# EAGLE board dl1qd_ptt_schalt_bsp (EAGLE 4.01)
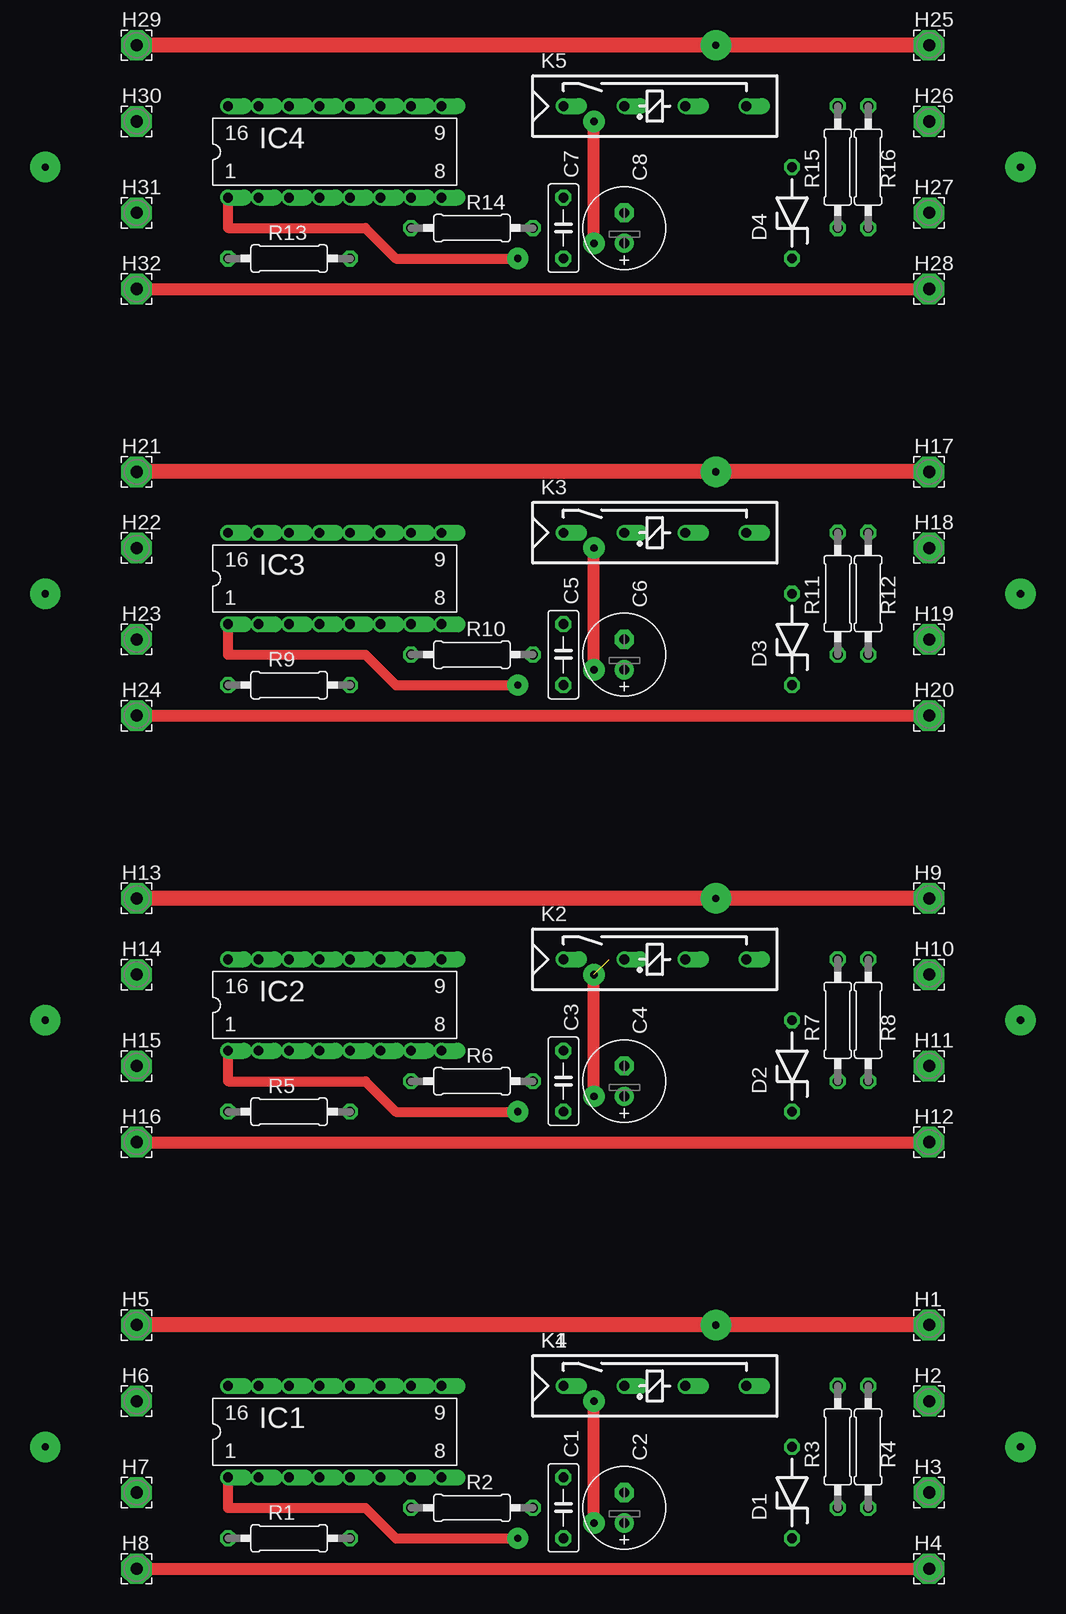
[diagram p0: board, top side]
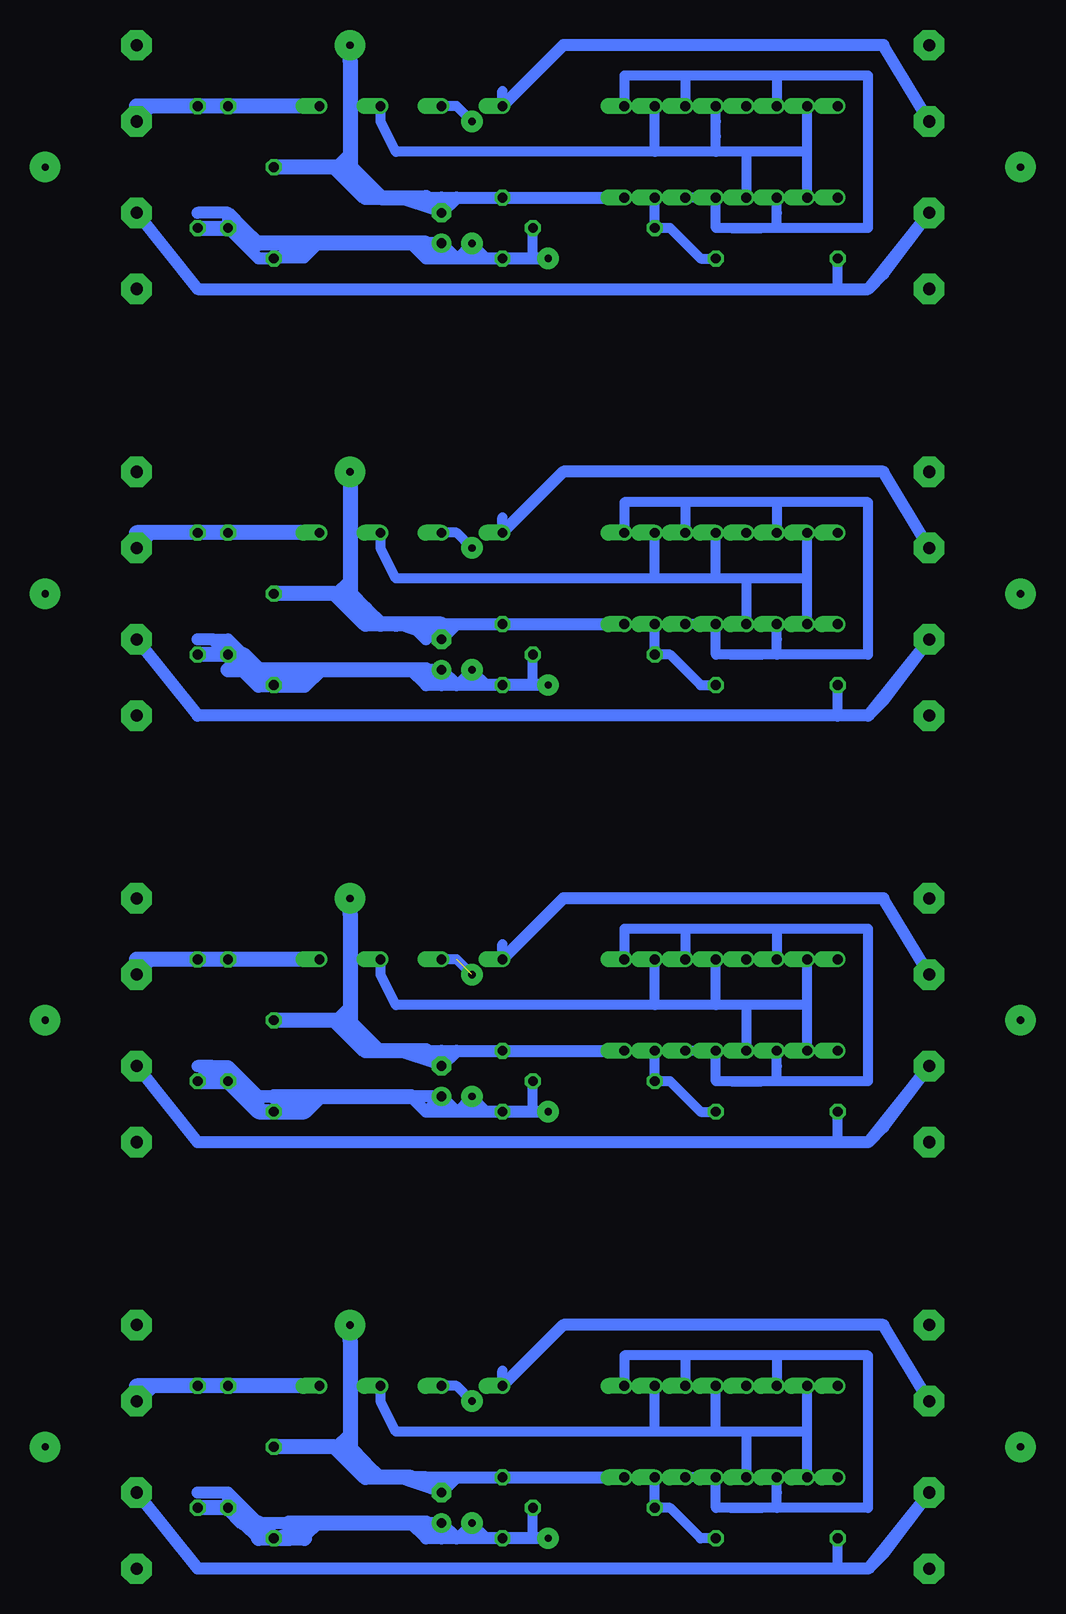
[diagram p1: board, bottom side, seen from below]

No outline drawn. Coordinates in mm, seen from the top.
Copper layers used: Top, Bottom

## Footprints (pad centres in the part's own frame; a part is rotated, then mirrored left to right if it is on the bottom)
C050-025X075 = drill 0.813 octagon: 1 -2.54,0; 2 2.54,0
E2,5-7 = drill 0.813 pad 1.6 round: + -1.27,0 | drill 0.813 pad 1.6 octagon: - 1.27,0
ZDIO-7.5 = drill 0.813 octagon: A -3.81,0; K 3.81,0
2,54/1,0 = drill 1.016 pad 2.54 octagon: 1 0,0
DIL16 = drill 0.813 offset: 1 -8.89,-3.81; 2 -6.35,-3.81; 3 -3.81,-3.81; 4 -1.27,-3.81; 5 1.27,-3.81; 6 3.81,-3.81; 7 6.35,-3.81; 8 8.89,-3.81; 9 8.89,3.81; 10 6.35,3.81; 11 3.81,3.81; 12 1.27,3.81; 13 -1.27,3.81; 14 -3.81,3.81; 15 -6.35,3.81; 16 -8.89,3.81
REED = drill 0.813 offset: 1 -17.78,2.54; 3 -12.7,2.54; 5 -7.62,2.54; 7 -2.54,2.54
0207/10 = drill 0.813 octagon: 1 -5.08,0; 2 5.08,0

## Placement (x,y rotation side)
C1  0.1µ  [C050-025X075]  48.26,69.85 90 top
C2  100µ  [E2,5-7]  53.34,69.85 90 top
C3  0.1µ  [C050-025X075]  48.26,105.41 90 top
C4  100µ  [E2,5-7]  53.34,105.41 90 top
C5  0.1µ  [C050-025X075]  48.26,140.97 90 top
C6  100µ  [E2,5-7]  53.34,140.97 90 top
C7  0.1µ  [C050-025X075]  48.26,176.53 90 top
C8  100µ  [E2,5-7]  53.34,176.53 90 top
D1  5.1  [ZDIO-7.5]  67.31,71.12 270 top
D2  5.1  [ZDIO-7.5]  67.31,106.68 270 top
D3  5.1  [ZDIO-7.5]  67.31,142.24 270 top
D4  5.1  [ZDIO-7.5]  67.31,177.8 270 top
H1  [2,54/1,0]  78.74,85.09 0 top
H2  [2,54/1,0]  78.74,78.74 0 top
H3  [2,54/1,0]  78.74,71.12 0 top
H4  [2,54/1,0]  78.74,64.77 0 top
H5  [2,54/1,0]  12.7,85.09 0 top
H6  [2,54/1,0]  12.7,78.74 0 top
H7  [2,54/1,0]  12.7,71.12 0 top
H8  [2,54/1,0]  12.7,64.77 0 top
H9  [2,54/1,0]  78.74,120.65 0 top
H10  [2,54/1,0]  78.74,114.3 0 top
H11  [2,54/1,0]  78.74,106.68 0 top
H12  [2,54/1,0]  78.74,100.33 0 top
H13  [2,54/1,0]  12.7,120.65 0 top
H14  [2,54/1,0]  12.7,114.3 0 top
H15  [2,54/1,0]  12.7,106.68 0 top
H16  [2,54/1,0]  12.7,100.33 0 top
H17  [2,54/1,0]  78.74,156.21 0 top
H18  [2,54/1,0]  78.74,149.86 0 top
H19  [2,54/1,0]  78.74,142.24 0 top
H20  [2,54/1,0]  78.74,135.89 0 top
H21  [2,54/1,0]  12.7,156.21 0 top
H22  [2,54/1,0]  12.7,149.86 0 top
H23  [2,54/1,0]  12.7,142.24 0 top
H24  [2,54/1,0]  12.7,135.89 0 top
H25  [2,54/1,0]  78.74,191.77 0 top
H26  [2,54/1,0]  78.74,185.42 0 top
H27  [2,54/1,0]  78.74,177.8 0 top
H28  [2,54/1,0]  78.74,171.45 0 top
H29  [2,54/1,0]  12.7,191.77 0 top
H30  [2,54/1,0]  12.7,185.42 0 top
H31  [2,54/1,0]  12.7,177.8 0 top
H32  [2,54/1,0]  12.7,171.45 0 top
IC1  4049  [DIL16]  29.21,76.2 0 top
IC2  4049  [DIL16]  29.21,111.76 0 top
IC3  4049  [DIL16]  29.21,147.32 0 top
IC4  4049  [DIL16]  29.21,182.88 0 top
K1  [REED]  66.04,77.47 0 top
K2  [REED]  66.04,113.03 0 top
K3  [REED]  66.04,148.59 0 top
K4  [REED]  66.04,77.47 0 top
K5  [REED]  66.04,184.15 0 top
R1  56k  [0207/10]  25.4,67.31 0 top
R2  1M  [0207/10]  40.64,69.85 0 top
R3  1k  [0207/10]  71.12,74.93 90 top
R4  1k  [0207/10]  73.66,74.93 90 top
R5  56k  [0207/10]  25.4,102.87 0 top
R6  1M  [0207/10]  40.64,105.41 0 top
R7  1k  [0207/10]  71.12,110.49 90 top
R8  1k  [0207/10]  73.66,110.49 90 top
R9  56k  [0207/10]  25.4,138.43 0 top
R10  1M  [0207/10]  40.64,140.97 0 top
R11  1k  [0207/10]  71.12,146.05 90 top
R12  1k  [0207/10]  73.66,146.05 90 top
R13  56k  [0207/10]  25.4,173.99 0 top
R14  1M  [0207/10]  40.64,176.53 0 top
R15  1k  [0207/10]  71.12,181.61 90 top
R16  1k  [0207/10]  73.66,181.61 90 top

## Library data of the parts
C1-C8 R1-R16 = rcl
D1-D4 = diode
H1-H32 = wirepad
IC1-IC4 = 40xx
K1-K5 = relay

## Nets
S$1: C2.+ D1.K IC1.1 K1.3 R2.2 R3.1 R4.1
S$2: IC1.2 IC1.4 IC1.10 IC1.12 IC1.15 K1.5
S$3: IC1.3 IC1.5 IC1.6 IC1.9 IC1.11 IC1.14
S$4: H4.1 H8.1
S$6: C1.2 C2.- D1.A H1.1 H5.1 IC1.8
S$7: IC1.7 R2.1
S$8: H3.1 H7.1 R1.1
S$9: R1.2
S$11: H2.1 K1.7
S$12: H6.1 K1.1

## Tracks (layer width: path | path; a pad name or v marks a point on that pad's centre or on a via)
S$1  (via drill 0.61 pad 1.78)
  Top 0.813: v44.45,67.31 34.29,67.31 31.75,69.85 20.32,69.85 IC1.1
  Top 1.016: v50.8,68.58 v50.8,78.74
  Bottom 0.813: 66.04,67.31 64.77,67.31 63.5,68.58 | K1.3 52.07,80.01 v50.8,78.74 | 49.53,67.31 v50.8,68.58 | 50.8,67.31 v50.8,68.58 | 50.8,67.31 49.53,67.31 | 52.07,67.31 50.8,67.31 | 52.07,67.31 49.53,67.31 | 52.07,67.31 v50.8,68.58 | 48.26,67.31 49.53,67.31 | 45.72,67.31 R2.2 | 45.72,67.31 48.26,67.31 | 45.72,67.31 v44.45,67.31 48.26,67.31 | R3.1 R4.1 R3.1
  Bottom 1.016: 71.12,71.12 73.66,71.12 | R4.1 R3.1 71.12,71.12 | 69.85,69.85 71.12,71.12 | 69.85,69.85 69.85,68.58 68.58,67.31 D1.K 63.5,68.58 | 69.85,69.85 68.58,68.58 66.04,68.58 63.5,68.58 | 55.88,68.58 63.5,68.58 | 54.61,67.31 55.88,68.58 | 55.88,68.58 54.61,68.58 C2.+ | C2.+ 54.61,67.31 | 53.34,67.31 54.61,67.31 | 53.34,67.31 C2.+ | 52.07,67.31 53.34,67.31 | 52.07,67.31 C2.+ | v44.45,67.31 52.07,67.31
  Bottom 1.27: R3.1 R4.1 R3.1 | R3.1 69.85,68.58 68.58,68.58 D1.K 66.04,67.31 | 64.77,67.31 68.58,67.31 | 54.61,68.58 66.04,68.58
S$2
  Bottom 0.813: IC1.2 22.86,76.2 | 22.86,76.2 IC1.15 | 22.86,76.2 27.94,76.2 | 27.94,76.2 30.48,76.2 | 30.48,76.2 35.56,76.2 | 35.56,76.2 IC1.10 | 35.56,76.2 57.15,76.2 58.42,78.74 K1.5 | 27.94,76.2 IC1.4 | 30.48,76.2 IC1.12
S$3
  Bottom 0.61: 25.4,71.12 IC1.3
  Bottom 0.813: 25.4,82.55 17.78,82.55 17.78,69.85 25.4,69.85 | 25.4,82.55 IC1.14 | 25.4,82.55 33.02,82.55 | 33.02,82.55 IC1.11 | 33.02,82.55 38.1,82.55 IC1.9 | IC1.6 IC1.5 30.48,69.85 29.21,69.85 | 29.21,69.85 26.67,69.85 | 25.4,69.85 25.4,71.12 | 25.4,69.85 IC1.3 | 25.4,69.85 29.21,69.85
S$4
  Top 1.016: H8.1 H4.1
S$5
  Bottom 0.813: 22.86,143.51 22.86,147.32 | 22.86,147.32 22.86,151.13 | 22.86,147.32 27.94,147.32 | 27.94,147.32 30.48,147.32 | 30.48,147.32 35.56,147.32 | 35.56,147.32 35.56,151.13 | 35.56,147.32 57.15,147.32 58.42,149.86 58.42,151.13 | 30.48,147.32 30.48,151.13 | 27.94,147.32 27.94,143.51
S$6  (via drill 0.61 pad 2.54)
  Top 1.016: H1.1 v60.96,85.09 H5.1
  Top 1.27: H1.1 H5.1
  Bottom 0.813: 60.96,74.93 60.96,76.2 62.23,74.93 60.96,73.66 | 57.15,72.39 C2.- 54.61,72.39 53.34,72.39 52.07,72.39 C1.2 IC1.8
  Bottom 1.016: 60.96,74.93 62.23,74.93 | 53.34,72.39 C2.- 52.07,72.39 | 52.07,72.39 IC1.8 | 52.07,72.39 54.61,72.39 55.88,72.39 57.15,72.39 | 57.15,72.39 58.42,72.39 59.69,73.66 | 60.96,74.93 59.69,73.66 | 59.69,73.66 59.69,72.39 | 59.69,72.39 57.15,72.39 | v60.96,85.09 60.96,83.82 | 59.69,72.39 60.96,73.66 60.96,74.93
  Bottom 1.27: D1.A 62.23,74.93 59.69,72.39 55.88,72.39 | 60.96,83.82 60.96,74.93
S$7
  Bottom 0.813: R2.1 IC1.7
S$8
  Bottom 0.813: 20.32,64.77 R1.1
  Bottom 1.016: 17.78,64.77 20.32,64.77 73.66,64.77 | 17.78,64.77 16.51,66.04 H7.1 17.78,64.77 | 73.66,64.77 H3.1 | 17.78,64.77 73.66,64.77
S$9
  Bottom 0.813: R1.2 31.75,67.31 34.29,69.85 35.56,69.85
S$10  (via drill 0.61 pad 2.54)
  other vias: 5.08,74.93
S$11
  Bottom 1.27: K1.7 77.47,80.01 | 77.47,80.01 H2.1 | 77.47,80.01 78.74,80.01
S$12
  Bottom 0.813: K1.1 48.26,81.28
  Bottom 1.016: K1.1 43.18,85.09 16.51,85.09 H6.1
S$13  (via drill 0.61 pad 2.54)
  other vias: 86.36,74.93
S$14
  Bottom 0.813: 22.86,107.95 22.86,111.76 | 22.86,111.76 22.86,115.57 | 22.86,111.76 27.94,111.76 | 27.94,111.76 30.48,111.76 | 30.48,111.76 35.56,111.76 | 35.56,111.76 35.56,115.57 | 35.56,111.76 57.15,111.76 58.42,114.3 58.42,115.57 | 27.94,111.76 27.94,107.95 | 30.48,111.76 30.48,115.57
S$15
  Bottom 0.61: 25.4,106.68 25.4,107.95
  Bottom 0.813: 25.4,118.11 17.78,118.11 17.78,105.41 25.4,105.41 | 25.4,118.11 25.4,115.57 | 25.4,118.11 33.02,118.11 | 33.02,118.11 33.02,115.57 | 33.02,118.11 38.1,118.11 38.1,115.57 | 33.02,107.95 30.48,107.95 30.48,105.41 29.21,105.41 | 29.21,105.41 26.67,105.41 | 25.4,105.41 25.4,106.68 | 25.4,105.41 25.4,107.95 | 25.4,105.41 29.21,105.41
S$16
  Bottom 0.813: 53.34,115.57 52.07,115.57 50.8,114.3
S$17
  Bottom 0.813: 35.56,105.41 35.56,107.95
S$18
  Bottom 0.813: 20.32,100.33 20.32,102.87
  Bottom 1.016: 17.78,100.33 20.32,100.33 73.66,100.33 | 17.78,100.33 16.51,101.6 12.7,106.68 17.78,100.33 | 73.66,100.33 78.74,106.68 | 17.78,100.33 73.66,100.33
S$19
  Top 1.016: 12.7,100.33 78.74,100.33
S$20  (via drill 0.61 pad 1.78)  (1 unrouted)
  Top 0.813: v44.45,102.87 34.29,102.87 31.75,105.41 20.32,105.41 20.32,107.95
  Top 1.016: v50.8,104.14 50.8,114.3
  Bottom 0.813: 67.31,102.87 66.04,102.87 | 50.8,102.87 49.53,102.87 | v50.8,104.14 50.8,102.87 | v50.8,104.14 49.53,102.87 | 52.07,102.87 v50.8,104.14 | 52.07,102.87 50.8,102.87 | 52.07,102.87 49.53,102.87 | 48.26,102.87 49.53,102.87 | 45.72,102.87 45.72,105.41 | 45.72,102.87 48.26,102.87 | 45.72,102.87 v44.45,102.87 48.26,102.87
  Bottom 1.016: 63.5,104.14 67.31,102.87 68.58,102.87 | 54.61,102.87 55.88,104.14 53.34,104.14 | 53.34,104.14 54.61,102.87 | 53.34,102.87 54.61,102.87 | 53.34,102.87 53.34,104.14 | 52.07,102.87 53.34,102.87 | 52.07,102.87 53.34,104.14 | v44.45,102.87 52.07,102.87 | 71.12,105.41 69.85,105.41 68.58,104.14 | 68.58,102.87 68.58,104.14 | 69.85,104.14 68.58,102.87 | 72.39,106.68 73.66,105.41 | 72.39,106.68 71.12,106.68 68.58,104.14 | 68.58,104.14 67.31,104.14 | 67.31,104.14 64.77,104.14 | 67.31,104.14 69.85,104.14 | 69.85,104.14 71.12,105.41 | 71.12,105.41 72.39,106.68 | 72.39,106.68 73.66,106.68
  Bottom 1.27: 68.58,102.87 71.12,105.41 73.66,105.41 | 68.58,102.87 66.04,102.87 | 66.04,102.87 64.77,102.87 | 67.31,104.14 63.5,104.14 | 63.5,104.14 55.88,104.14 | 66.04,102.87 64.77,104.14 63.5,104.14 | 63.5,104.14 64.77,102.87 | 64.77,102.87 68.58,102.87
S$21
  Bottom 0.813: 30.48,102.87 31.75,102.87 34.29,105.41 35.56,105.41
S$22
  Bottom 1.016: 78.74,114.3 77.47,115.57 64.77,115.57 63.5,115.57
  Bottom 1.27: 64.77,115.57 78.74,115.57 78.74,114.3
S$23
  Bottom 0.813: 48.26,115.57 48.26,116.84
  Bottom 1.016: 48.26,115.57 43.18,120.65 16.51,120.65 12.7,114.3
S$24  (via drill 0.61 pad 2.54)
  Top 1.016: 78.74,120.65 v60.96,120.65 12.7,120.65
  Top 1.27: 78.74,120.65 12.7,120.65
  Bottom 0.813: 60.96,110.49 60.96,111.76 62.23,110.49 60.96,109.22 | 58.42,107.95 57.15,107.95 | 57.15,107.95 53.34,106.68 54.61,107.95 53.34,107.95 52.07,107.95 | 57.15,107.95 55.88,107.95
  Bottom 1.016: 60.96,110.49 62.23,110.49 | 53.34,107.95 53.34,106.68 52.07,107.95 | 52.07,107.95 38.1,107.95 | 55.88,107.95 54.61,107.95 | 54.61,107.95 52.07,107.95 | 54.61,107.95 58.42,107.95 | 58.42,107.95 59.69,107.95 60.96,109.22 60.96,110.49 | 60.96,110.49 60.96,119.38 v60.96,120.65 | 60.96,110.49 58.42,107.95
  Bottom 1.27: 67.31,110.49 62.23,110.49 59.69,107.95 54.61,107.95 | 60.96,119.38 60.96,109.22
S$25  (via drill 0.61 pad 2.54)
  other vias: 5.08,110.49
S$26  (via drill 0.61 pad 2.54)
  other vias: 86.36,110.49
S$27
  Bottom 0.61: 25.4,142.24 25.4,143.51
  Bottom 0.813: 25.4,153.67 17.78,153.67 17.78,140.97 25.4,140.97 | 25.4,153.67 25.4,151.13 | 25.4,153.67 33.02,153.67 | 33.02,153.67 33.02,151.13 | 33.02,153.67 38.1,153.67 38.1,151.13 | 33.02,143.51 30.48,143.51 30.48,140.97 29.21,140.97 | 29.21,140.97 26.67,140.97 | 25.4,140.97 25.4,142.24 | 25.4,140.97 25.4,143.51 | 25.4,140.97 29.21,140.97
S$28  (via drill 0.61 pad 1.78)
  Top 0.813: v44.45,138.43 34.29,138.43 31.75,140.97 20.32,140.97 20.32,143.51
  Top 1.016: v50.8,139.7 v50.8,149.86
  Bottom 0.813: 50.8,138.43 49.53,138.43 | v50.8,139.7 50.8,138.43 | v50.8,139.7 49.53,138.43 | 52.07,138.43 v50.8,139.7 | 52.07,138.43 50.8,138.43 | 52.07,138.43 49.53,138.43 | 48.26,138.43 49.53,138.43 | 45.72,138.43 45.72,140.97 | 45.72,138.43 48.26,138.43 | 45.72,138.43 v44.45,138.43 48.26,138.43 | 53.34,151.13 52.07,151.13 v50.8,149.86
  Bottom 1.016: 69.85,139.7 68.58,138.43 67.31,139.7 68.58,139.7 69.85,139.7 | 69.85,139.7 71.12,140.97 72.39,142.24 | 63.5,139.7 67.31,138.43 | 54.61,138.43 55.88,139.7 | 53.34,139.7 54.61,139.7 | 53.34,139.7 54.61,138.43 | 53.34,138.43 54.61,138.43 | 53.34,138.43 53.34,139.7 | 52.07,138.43 53.34,138.43 | 52.07,138.43 53.34,139.7 | v44.45,138.43 52.07,138.43 | 69.85,139.7 69.85,140.97 71.12,142.24 72.39,142.24 | 72.39,142.24 73.66,142.24
  Bottom 1.27: 66.04,139.7 67.31,139.7 | 64.77,139.7 66.04,139.7 | 54.61,139.7 55.88,139.7 63.5,139.7 | 66.04,139.7 71.12,139.7 | 71.12,140.97 69.85,140.97 | 69.85,140.97 68.58,139.7 68.58,138.43 | 68.58,138.43 67.31,138.43 66.04,138.43 | 68.58,138.43 71.12,140.97 | 71.12,140.97 73.66,140.97 | 63.5,139.7 64.77,139.7 | 64.77,139.7 66.04,138.43 | 66.04,138.43 64.77,138.43 63.5,139.7 | 71.12,140.97 69.85,140.97
S$29
  Bottom 0.813: 35.56,140.97 35.56,143.51
S$30
  Bottom 0.813: 20.32,135.89 20.32,138.43
  Bottom 1.016: 17.78,135.89 20.32,135.89 73.66,135.89 | 17.78,135.89 16.51,137.16 12.7,142.24 17.78,135.89 | 73.66,135.89 78.74,142.24 | 17.78,135.89 73.66,135.89
S$31
  Top 1.016: 12.7,135.89 78.74,135.89
S$32  (via drill 0.61 pad 1.78)  (1 unrouted)
  Bottom 0.813: 52.07,115.57 53.34,115.57
  other vias: 50.8,114.3
S$33
  Bottom 0.813: 30.48,138.43 31.75,138.43 34.29,140.97 35.56,140.97
S$34
  Bottom 1.016: 78.74,149.86 77.47,151.13 63.5,151.13
  Bottom 1.27: 63.5,151.13 78.74,151.13 78.74,149.86
S$35
  Bottom 0.813: 48.26,151.13 48.26,152.4
  Bottom 1.016: 48.26,151.13 43.18,156.21 16.51,156.21 12.7,149.86
S$36  (via drill 0.61 pad 2.54)
  Top 1.016: 78.74,156.21 v60.96,156.21 12.7,156.21
  Top 1.27: 78.74,156.21 12.7,156.21
  Bottom 0.813: 60.96,146.05 60.96,147.32 62.23,146.05 60.96,144.78 | 57.15,143.51 53.34,142.24 54.61,143.51
  Bottom 1.016: 62.23,146.05 60.96,146.05 58.42,143.51 | 53.34,143.51 53.34,142.24 52.07,143.51 | 52.07,143.51 38.1,143.51 | 55.88,143.51 54.61,143.51 53.34,143.51 | 53.34,143.51 52.07,143.51 | 54.61,142.24 55.88,143.51 | 60.96,144.78 59.69,143.51 58.42,143.51 | 58.42,143.51 57.15,143.51 55.88,143.51
  Bottom 1.27: 67.31,146.05 62.23,146.05 59.69,143.51 | v60.96,156.21 60.96,146.05 | 60.96,146.05 60.96,144.78 59.69,144.78 | 59.69,144.78 58.42,143.51 | 53.34,143.51 57.15,143.51 59.69,143.51 | 59.69,143.51 59.69,144.78 | 59.69,144.78 60.96,146.05
S$37  (via drill 0.61 pad 2.54)
  other vias: 5.08,146.05
S$38  (via drill 0.61 pad 2.54)
  other vias: 86.36,146.05
S$39
  Bottom 0.406: 30.48,185.42 30.48,186.69
  Bottom 0.813: 22.86,179.07 22.86,182.88 | 22.86,182.88 22.86,186.69 | 22.86,182.88 27.94,182.88 | 27.94,182.88 30.48,182.88 | 30.48,184.15 30.48,185.42 | 30.48,182.88 30.48,184.15 | 30.48,182.88 35.56,182.88 | 35.56,182.88 35.56,186.69 | 35.56,182.88 57.15,182.88 58.42,185.42 58.42,186.69 | 27.94,182.88 27.94,179.07 | 30.48,184.15 30.48,186.69
S$40
  Bottom 0.61: 25.4,177.8 25.4,179.07
  Bottom 0.813: 25.4,189.23 17.78,189.23 17.78,176.53 25.4,176.53 | 25.4,189.23 25.4,186.69 | 25.4,189.23 33.02,189.23 | 33.02,189.23 33.02,186.69 | 33.02,189.23 38.1,189.23 38.1,186.69 | 33.02,179.07 30.48,179.07 30.48,176.53 29.21,176.53 | 29.21,176.53 26.67,176.53 | 25.4,176.53 25.4,177.8 | 25.4,176.53 25.4,179.07 | 25.4,176.53 29.21,176.53
S$41  (via drill 0.61 pad 1.78)
  Top 0.813: v44.45,173.99 34.29,173.99 31.75,176.53 20.32,176.53 20.32,179.07
  Top 1.016: v50.8,175.26 v50.8,185.42
  Bottom 0.813: 68.58,173.99 64.77,173.99 63.5,175.26 | 50.8,173.99 49.53,173.99 | v50.8,175.26 50.8,173.99 | v50.8,175.26 49.53,173.99 | 52.07,173.99 v50.8,175.26 | 52.07,173.99 50.8,173.99 | 52.07,173.99 49.53,173.99 | 48.26,173.99 49.53,173.99 | 45.72,173.99 45.72,176.53 | 45.72,173.99 48.26,173.99 | 45.72,173.99 v44.45,173.99 48.26,173.99 | 53.34,186.69 52.07,186.69 v50.8,185.42
  Bottom 1.016: 69.85,175.26 68.58,173.99 67.31,173.99 63.5,175.26 | 55.88,175.26 63.5,175.26 | 55.88,175.26 54.61,173.99 | 53.34,175.26 54.61,175.26 55.88,175.26 | 53.34,175.26 54.61,173.99 | 53.34,173.99 54.61,173.99 | 53.34,173.99 53.34,175.26 | 52.07,173.99 53.34,173.99 | 52.07,173.99 53.34,175.26 | v44.45,173.99 52.07,173.99 | 69.85,176.53 69.85,175.26 | 68.58,175.26 69.85,176.53 | 63.5,175.26 68.58,175.26 | 68.58,175.26 69.85,175.26 | 69.85,175.26 71.12,176.53 71.12,177.8 | 71.12,177.8 73.66,177.8 | 71.12,177.8 69.85,176.53
  Bottom 1.27: 54.61,175.26 68.58,175.26 | 73.66,176.53 71.12,176.53
S$42
  Bottom 0.813: 35.56,176.53 35.56,179.07
S$43
  Bottom 0.813: 20.32,171.45 20.32,173.99
  Bottom 1.016: 17.78,171.45 20.32,171.45 73.66,171.45 | 17.78,171.45 16.51,172.72 12.7,177.8 17.78,171.45 | 78.74,177.8 73.66,171.45 | 73.66,171.45 17.78,171.45
S$44
  Top 1.016: 12.7,171.45 78.74,171.45
S$46
  Bottom 0.813: 30.48,173.99 31.75,173.99 34.29,176.53 35.56,176.53
S$47
  Bottom 1.016: 78.74,185.42 77.47,186.69 64.77,186.69 63.5,186.69
  Bottom 1.27: 64.77,186.69 78.74,186.69 78.74,185.42
S$48
  Bottom 0.813: 48.26,186.69 48.26,187.96
  Bottom 1.016: 48.26,186.69 43.18,191.77 16.51,191.77 12.7,185.42
S$49  (via drill 0.61 pad 2.54)
  Top 1.016: 78.74,191.77 v60.96,191.77 12.7,191.77
  Top 1.27: 78.74,191.77 12.7,191.77
  Bottom 0.813: 60.96,181.61 60.96,182.88 62.23,181.61 60.96,180.34 | 58.42,179.07 57.15,179.07 | 57.15,179.07 53.34,177.8 54.61,179.07 | 57.15,179.07 55.88,179.07
  Bottom 1.016: v60.96,191.77 60.96,190.5 | 60.96,180.34 59.69,179.07 | 60.96,181.61 62.23,181.61 | 53.34,179.07 53.34,177.8 52.07,179.07 | 52.07,179.07 38.1,179.07 | 55.88,179.07 54.61,179.07 53.34,179.07 | 53.34,179.07 52.07,179.07
  Bottom 1.27: 67.31,181.61 62.23,181.61 59.69,179.07 58.42,179.07 | 60.96,190.5 60.96,181.61 | 60.96,181.61 60.96,180.34 | 60.96,181.61 58.42,179.07 | 58.42,179.07 54.61,179.07
S$50  (via drill 0.61 pad 2.54)
  other vias: 5.08,181.61
S$51  (via drill 0.61 pad 2.54)
  other vias: 86.36,181.61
